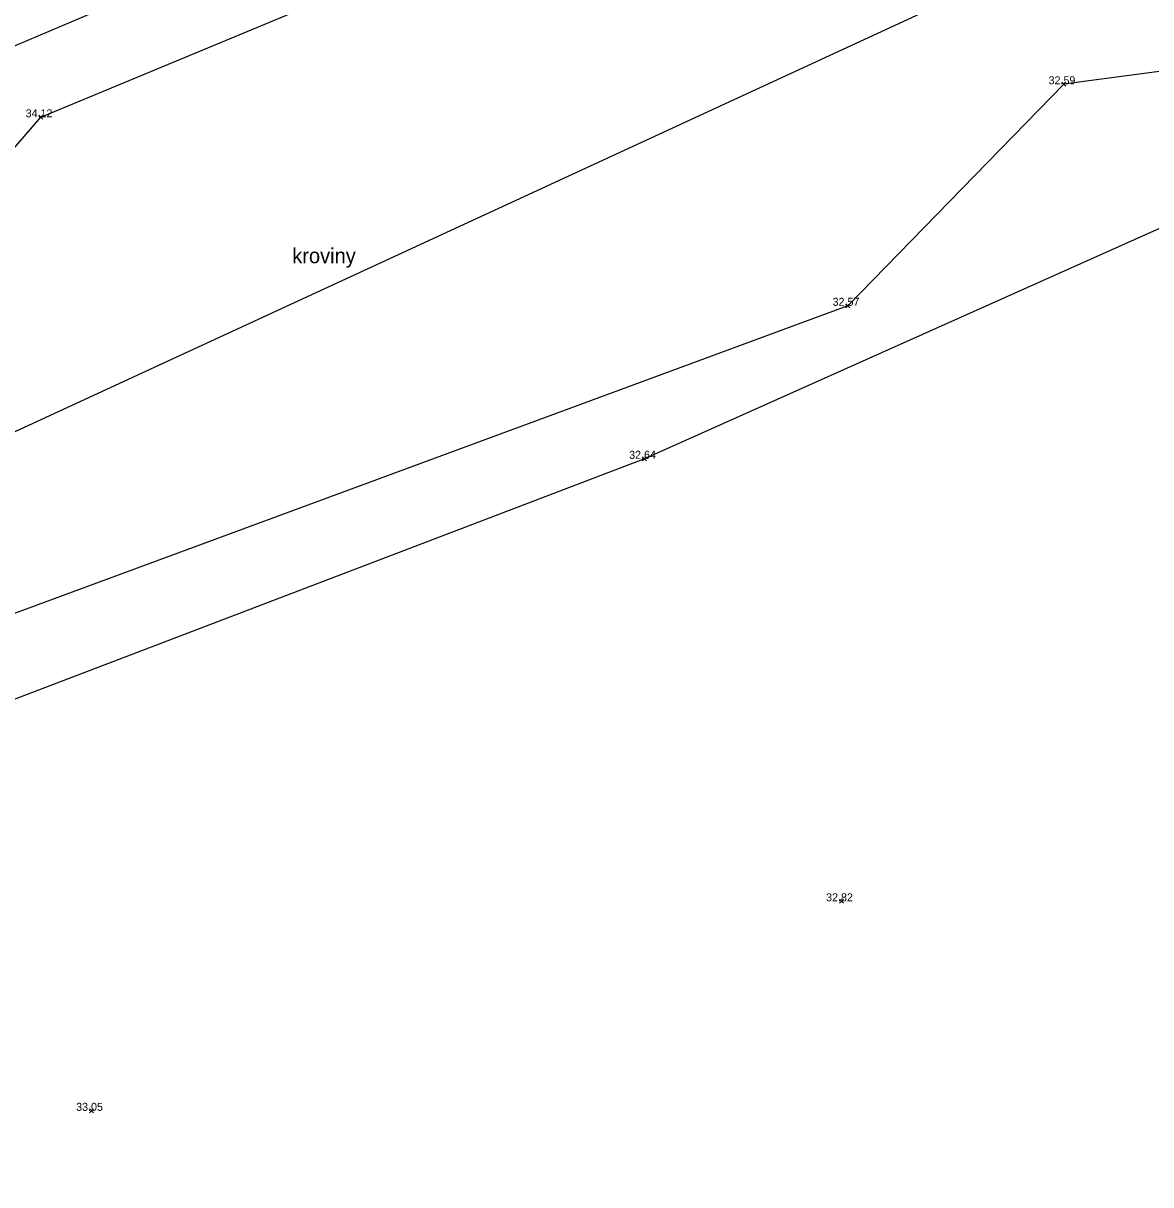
# Model space of a CAD drawing. Extents: x -772865 to -772533, y -1034366 to -1034132.
# Drawn here: x -772724.54 to -772701.99, y -1034264.08 to -1034240.85 of the extents above; entities that cross this region are included whole.
import ezdxf

# ---------------------------------------------------------------- set-up
doc = ezdxf.new("R2010")
doc.units = 0
for name, color, linetype in [('body', 7, 'Continuous'), ('KM_hranice', 7, 'Continuous'), ('mistni_popis', 7, 'Continuous'), ('oddeleni_ploch', 7, 'Continuous'), ('stromy_kere', 7, 'Continuous'), ('vyskove_koty', 7, 'Continuous')]:
    doc.layers.add(name, color=color, linetype=linetype)

msp = doc.modelspace()

# ---------------------------------------------------------------- linework, layer by layer
at = {"layer": 'body'}
for p, q in [((-772703.69, -1034242.11), (-772703.77, -1034242.03)), ((-772703.77, -1034242.11), (-772703.69, -1034242.03)), ((-772724.15, -1034242.77), (-772724.23, -1034242.69)), ((-772724.23, -1034242.77), (-772724.15, -1034242.69)), ((-772708.01, -1034246.54), (-772708.09, -1034246.46)), ((-772708.09, -1034246.54), (-772708.01, -1034246.46)), ((-772712.08, -1034249.6), (-772712.16, -1034249.52)), ((-772712.16, -1034249.6), (-772712.08, -1034249.52)), ((-772708.14, -1034258.45), (-772708.22, -1034258.37)), ((-772708.22, -1034258.45), (-772708.14, -1034258.37)), ((-772723.14, -1034262.64), (-772723.22, -1034262.56)), ((-772723.22, -1034262.64), (-772723.14, -1034262.56))]:
    msp.add_line(p, q, dxfattribs=at)
at = {"layer": 'KM_hranice'}
msp.add_line((-772692.32, -1034234.06), (-772741, -1034256.54), dxfattribs=at)
at = {"layer": 'oddeleni_ploch'}
for points in [[(-772574.1, -1034196.14), (-772586.87, -1034201.34), (-772598.23, -1034205.06), (-772614.53, -1034207.42), (-772626.93, -1034206.95), (-772636.66, -1034207.26), (-772647.96, -1034208.36), (-772659.39, -1034213.08), (-772672.58, -1034218.62), (-772687.49, -1034225.14), (-772703.01, -1034232.02), (-772714.35, -1034236.9), (-772728.88, -1034243.07), (-772737.97, -1034245.74), (-772746.8, -1034246.99), (-772753.85, -1034250.11), (-772762.71, -1034257.3), (-772782.05, -1034269.18), (-772797.09, -1034276.39), (-772810.61, -1034282.39), (-772816.13, -1034284.08), (-772822.76, -1034283.4), (-772826.73, -1034280.27)], [(-772569.67, -1034207.72), (-772578.35, -1034211.18), (-772588.33, -1034216.15), (-772592.11, -1034217.46), (-772598.89, -1034219.1), (-772610.21, -1034219.57), (-772621.14, -1034219.48), (-772637.34, -1034221.06), (-772647.54, -1034222.08), (-772674.34, -1034233.24), (-772685.01, -1034239.21), (-772697.33, -1034242.95), (-772712.12, -1034249.56), (-772725.85, -1034254.8), (-772738.85, -1034261.98), (-772750.37, -1034267.76), (-772764, -1034272.65), (-772783.9, -1034280.59), (-772796.38, -1034286.28), (-772810.31, -1034291.67), (-772823.61, -1034294.35), (-772828.52, -1034296.12), (-772827.01, -1034302.81), (-772823.23, -1034300.75)]]:
    msp.add_lwpolyline(points, dxfattribs=at)
at = {"layer": 'stromy_kere'}
for points in [[(-772765.65, -1034261.7), (-772757.35, -1034258.12), (-772757.45, -1034255.36), (-772753.97, -1034253.1), (-772751.37, -1034253.13), (-772749.46, -1034253.04), (-772745.29, -1034253.13), (-772741.93, -1034251.74), (-772739.6, -1034248.34), (-772733.8, -1034245.53), (-772729.53, -1034246.03), (-772725.99, -1034244.81), (-772724.19, -1034242.73), (-772713.9, -1034238.45), (-772703.51, -1034234.42), (-772694.98, -1034230.19)], [(-772697.8, -1034241.28), (-772703.73, -1034242.07), (-772708.05, -1034246.5), (-772725.99, -1034253.12), (-772730.64, -1034252.64), (-772736.35, -1034255.43), (-772738.23, -1034258.84), (-772742.19, -1034258.97), (-772751.86, -1034263.8), (-772757.95, -1034266.78), (-772758.48, -1034269.42), (-772764.72, -1034271.25), (-772777.99, -1034275.49), (-772780.54, -1034274.19), (-772782.8, -1034275.98), (-772782.89, -1034278.68), (-772790.87, -1034282.58), (-772810.31, -1034291.67)]]:
    msp.add_lwpolyline(points, dxfattribs=at)

# ---------------------------------------------------------------- texts
at = {"layer": 'mistni_popis'}
msp.add_text('kroviny', height=0.3, dxfattribs=at).set_placement((-772719.163, -1034245.648))
at = {"layer": 'vyskove_koty'}
for s, p in [('32.59', (-772704.035, -1034242.07)), ('34.12', (-772724.495, -1034242.73)), ('32.57', (-772708.355, -1034246.5)), ('32.64', (-772712.425, -1034249.56)), ('32.82', (-772708.485, -1034258.41)), ('33.05', (-772723.485, -1034262.6))]:
    msp.add_text(s, height=0.16, dxfattribs=at).set_placement(p)

doc.saveas('drawing.dxf')
